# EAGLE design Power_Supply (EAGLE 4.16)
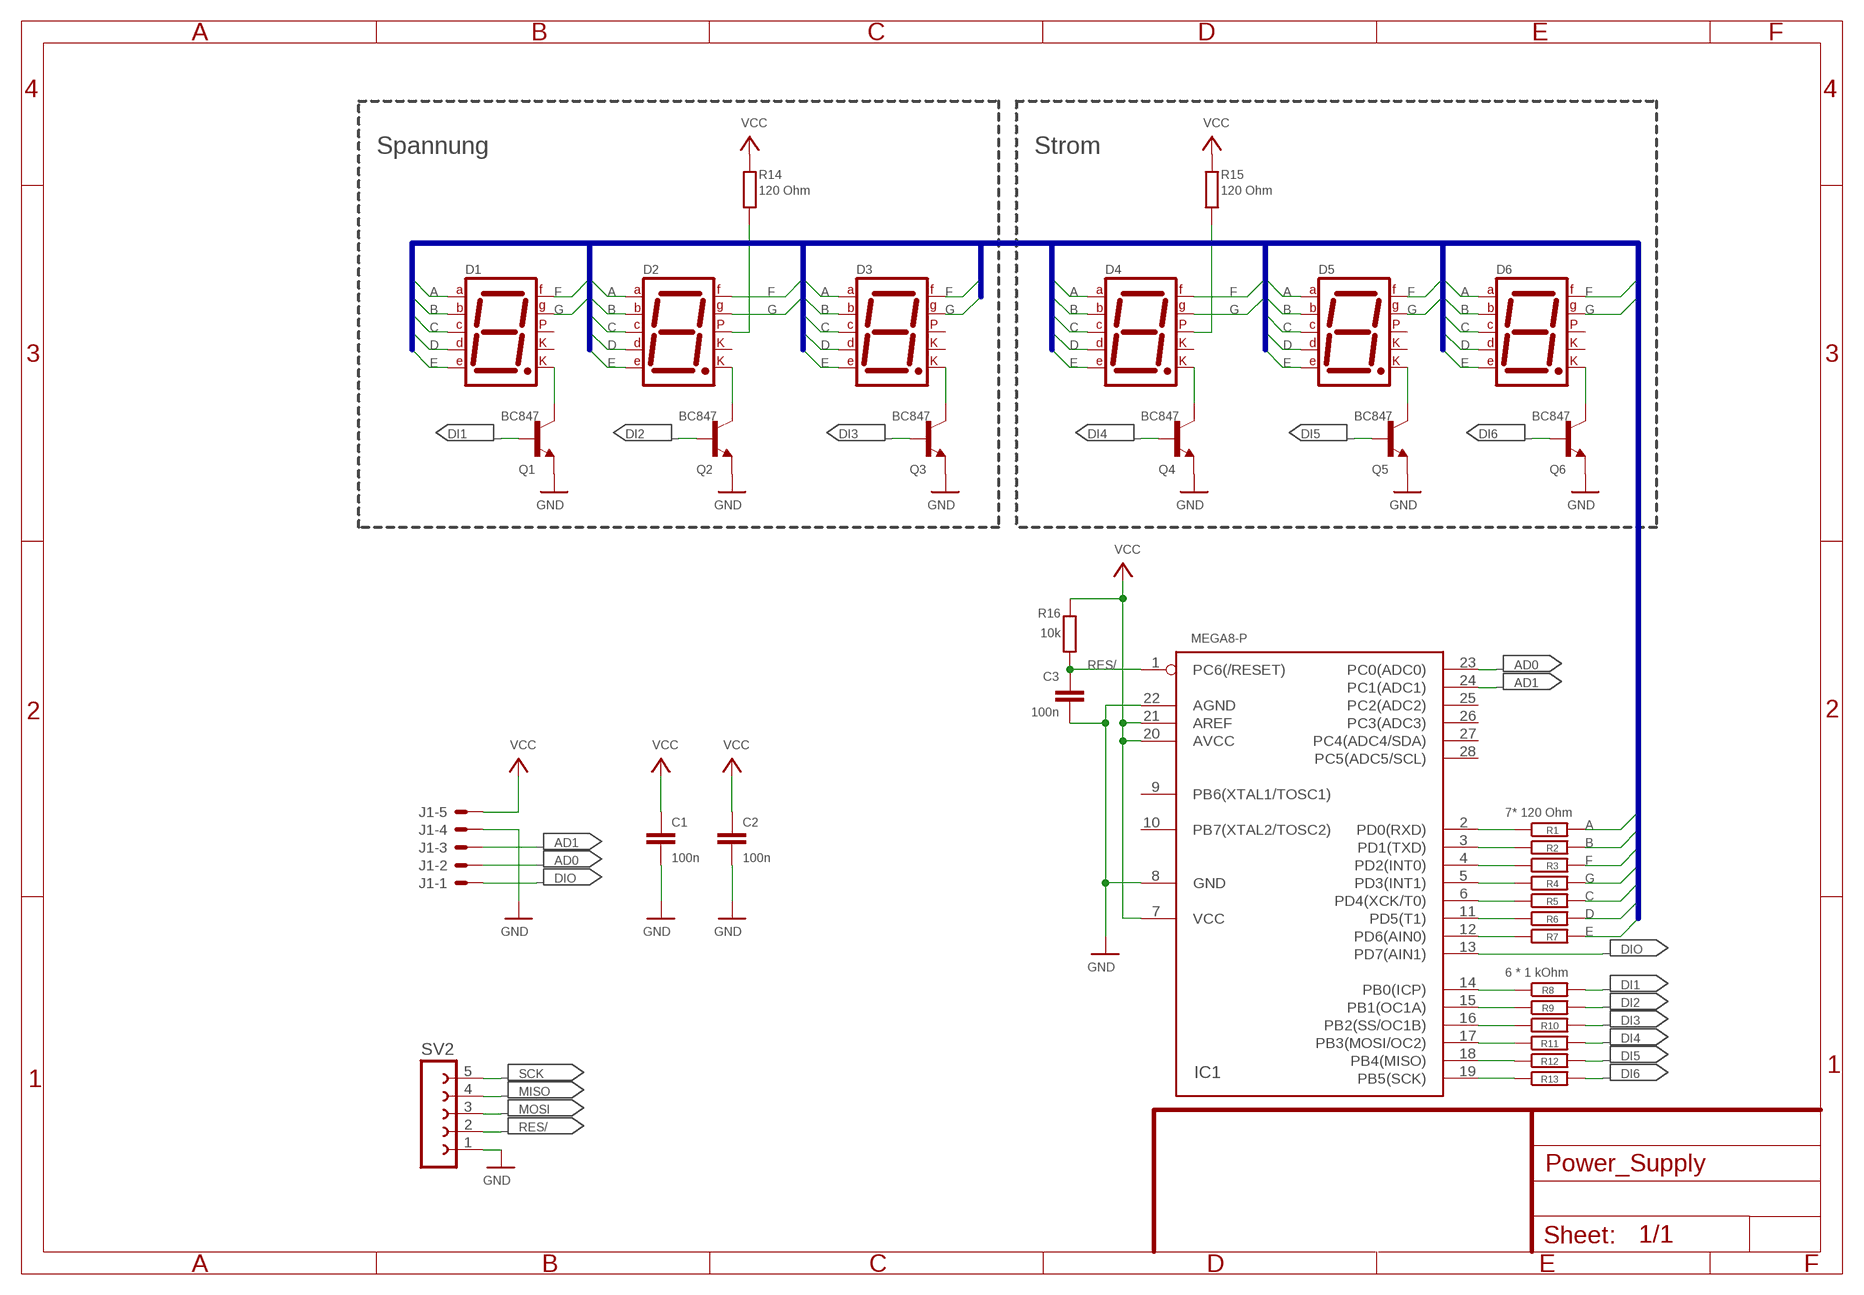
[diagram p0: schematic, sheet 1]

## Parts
C1  100n  C-EU025-025X050  [C025-025X050]
C2  100n  C-EU025-025X050  [C025-025X050]
C3  100n  C-EU025-025X050  [C025-025X050]
D1  7SEG-CK  [7SEG-13]
D2  7SEG-CK  [7SEG-13]
D3  7SEG-CK  [7SEG-13]
D4  7SEG-CK  [7SEG-13]
D5  7SEG-CK  [7SEG-13]
D6  7SEG-CK  [7SEG-13]
IC1  MEGA8-P  [DIL28-3]
J1  22-27-2051-05  [6410-05]
Q1  BC847  BC847BSMD  [SOT23]
Q2  BC847  BC847BSMD  [SOT23]
Q3  BC847  BC847BSMD  [SOT23]
Q4  BC847  BC847BSMD  [SOT23]
Q5  BC847  BC847BSMD  [SOT23]
Q6  BC847  BC847BSMD  [SOT23]
R1  7* 120 Ohm  R-EU_0207/10  [0207/10]
R2  R-EU_0207/10  [0207/10]
R3  R-EU_0207/10  [0207/10]
R4  R-EU_0207/10  [0207/10]
R5  R-EU_0207/10  [0207/10]
R6  R-EU_0207/10  [0207/10]
R7  R-EU_0207/10  [0207/10]
R8  6 * 1 kOhm  R-EU_0207/10  [0207/10]
R9  R-EU_0207/10  [0207/10]
R10  R-EU_0207/10  [0207/10]
R11  R-EU_0207/10  [0207/10]
R12  R-EU_0207/10  [0207/10]
R13  R-EU_0207/10  [0207/10]
R14  120 Ohm  R-EU_0207/10  [0207/10]
R15  120 Ohm  R-EU_0207/10  [0207/10]
R16  10k  R-EU_0207/10  [0207/10]
SV2  FE05-1  [FE05-1]

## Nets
A: D1.7(A) D2.7(A) D3.7(A) D4.7(A) D5.7(A) D6.7(A) R1.2
AD0: IC1.23(PC0(ADC0)) J1.2
AD1: IC1.24(PC1(ADC1)) J1.3
B: D1.6(B) D2.6(B) D3.6(B) D4.6(B) D5.6(B) D6.6(B) R2.2
C: D1.4(C) D2.4(C) D3.4(C) D4.4(C) D5.4(C) D6.4(C) R5.2
D: D1.2(D) D2.2(D) D3.2(D) D4.2(D) D5.2(D) D6.2(D) R6.2
DI1: Q1.1(B) R8.2
DI2: Q2.1(B) R9.2
DI3: Q3.1(B) R10.2
DI4: Q4.1(B) R11.2
DI5: Q5.1(B) R12.2
DI6: Q6.1(B) R13.2
DIO: IC1.13(PD7(AIN1)) J1.1
E: D1.1(E) D2.1(E) D3.1(E) D4.1(E) D5.1(E) D6.1(E) R7.2
F: D1.9(F) D2.9(F) D3.9(F) D4.9(F) D5.9(F) D6.9(F) R3.2
G: D1.10(G) D2.10(G) D3.10(G) D4.10(G) D5.10(G) D6.10(G) R4.2
GND: C1.2 C2.2 C3.2 IC1.8(GND) IC1.22(AGND) J1.4 Q1.2(E) Q2.2(E) Q3.2(E) Q4.2(E) Q5.2(E) Q6.2(E) SV2.1
MISO: IC1.18(PB4(MISO)) R12.1 SV2.4
MOSI: IC1.17(PB3(MOSI/OC2)) R11.1 SV2.3
N$1: IC1.2(PD0(RXD)) R1.1
N$2: IC1.3(PD1(TXD)) R2.1
N$3: IC1.4(PD2(INT0)) R3.1
N$4: IC1.5(PD3(INT1)) R4.1
N$5: IC1.6(PD4(XCK/T0)) R5.1
N$6: IC1.11(PD5(T1)) R6.1
N$7: IC1.12(PD6(AIN0)) R7.1
N$8: D1.8(CK2) Q1.3(C)
N$9: D2.8(CK2) Q2.3(C)
N$10: D3.8(CK2) Q3.3(C)
N$11: D4.8(CK2) Q4.3(C)
N$12: D5.8(CK2) Q5.3(C)
N$13: D6.8(CK2) Q6.3(C)
N$14: IC1.14(PB0(ICP)) R8.1
N$15: IC1.15(PB1(OC1A)) R9.1
N$16: IC1.16(PB2(SS/OC1B)) R10.1
N$20: D2.5(DP) R14.1
N$21: D4.5(DP) R15.1
RES/: C3.1 IC1.1(PC6(/RESET)) R16.1 SV2.2
SCK: IC1.19(PB5(SCK)) R13.1 SV2.5
VCC: C1.1 C2.1 IC1.7(VCC) IC1.20(AVCC) IC1.21(AREF) J1.5 R14.2 R15.2 R16.2
Unconnected: D1.3(CK1) D1.5(DP) D2.3(CK1) D3.3(CK1) D3.5(DP) D4.3(CK1) D5.3(CK1) D5.5(DP) D6.3(CK1) D6.5(DP) IC1.9(PB6(XTAL1/TOSC1)) IC1.10(PB7(XTAL2/TOSC2)) IC1.25(PC2(ADC2)) IC1.26(PC3(ADC3)) IC1.27(PC4(ADC4/SDA)) IC1.28(PC5(ADC5/SCL))

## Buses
A,B,C,D,E,F,G

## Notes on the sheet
- Spannung | Strom

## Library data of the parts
C1-C3 = rcl:C-EU: CAPACITOR, European symbol
D1-D6 = special:7SEG-CK: 7-segment DISPLAY single cathode, 13 mm
IC1 = avr-1:MEGA8-P: MICROCONTROLLER 8 Kbytes FLASH 1 kbytes SRAM 512 bytes EEPROM USART 4-channel 10 bit ADC 2-channel 8 bit ADC
J1 = con-molex:22-?-05: CONNECTOR wire to board 2.54 mm (.1 inch) pitch header
Q1-Q6 = transistor-npn:BC847*: NPN Transistor
R1-R16 = rcl:R-EU_: RESISTOR, European symbol
SV2 = con-lsta:FE05-1: FEMALE HEADER

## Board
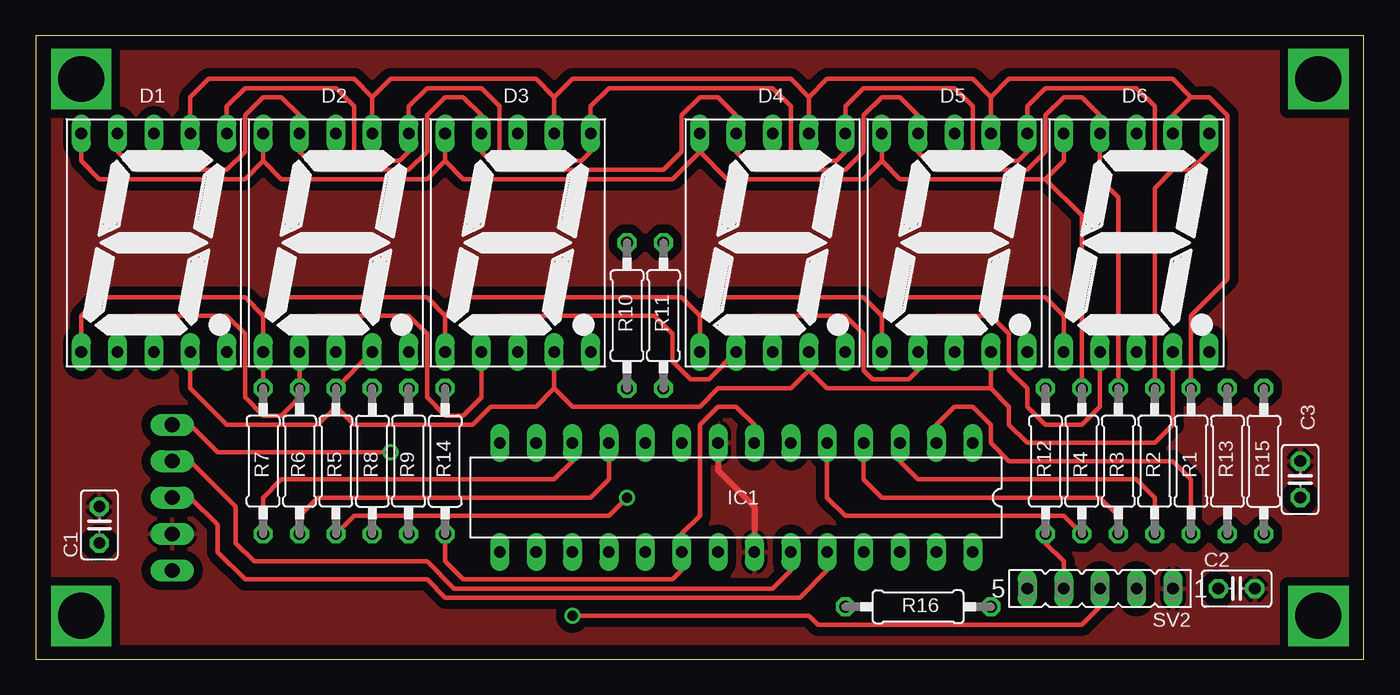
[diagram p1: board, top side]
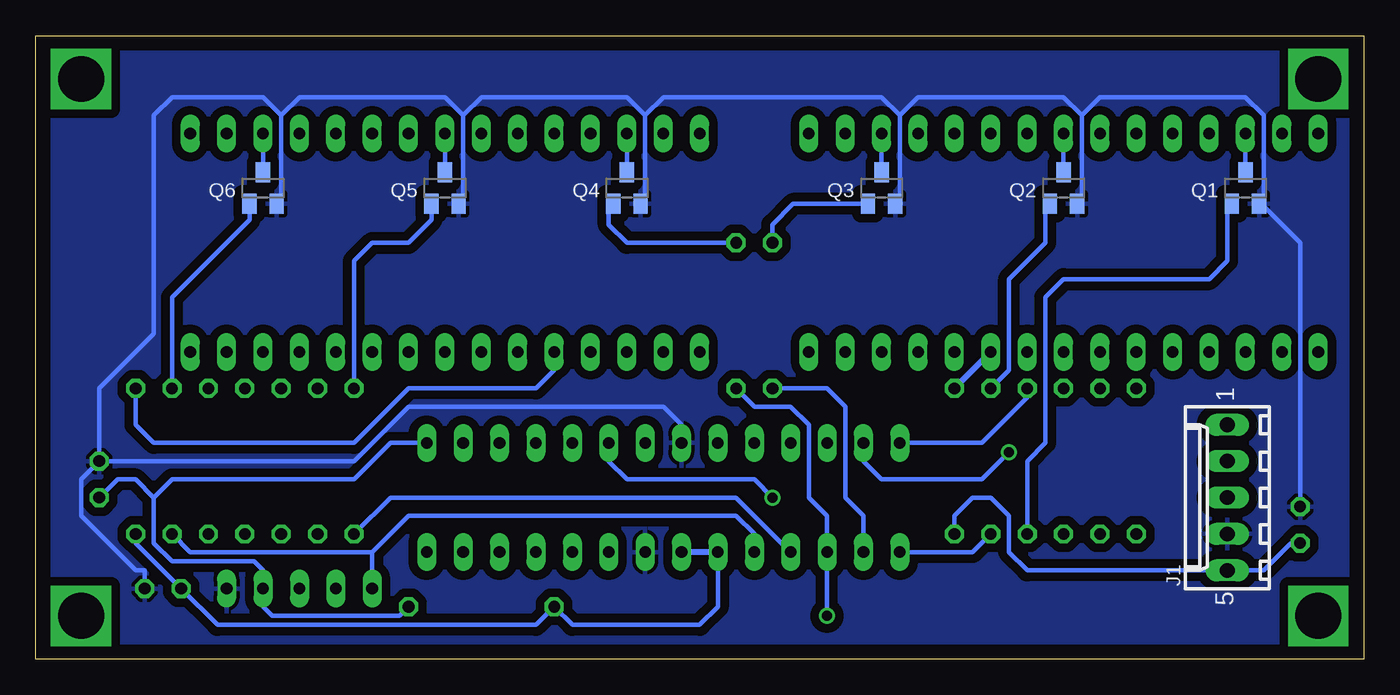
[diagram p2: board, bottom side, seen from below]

Size 92.69 x 43.48 mm. Coordinates in mm from the lower left corner, seen from the top.
Outline: 0,0 92.69,0 92.69,43.48 0,43.48 0,0
Copper layers (1*16): Top 0.035mm / dielectric 1.5mm / Bottom 0.035mm
Design rules "default": minimum track width 10mil, minimum drill 24mil, track to track 8mil, track to pad 8mil, pad to pad 8mil, via to via 8mil, smd to smd 8mil, copper to edge 40mil, drill to drill 8mil, minimum pad ring 10mil, minimum via ring 8mil, stop-mask expansion 4mil, vias tented up to drill 0mil, thermal gap 10mil

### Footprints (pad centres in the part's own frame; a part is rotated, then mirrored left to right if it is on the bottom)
C025-025X050 = drill 0.813 octagon: 1 -1.27,0; 2 1.27,0
7SEG-13 = drill 0.813 long: 1 -5.08,-7.62; 2 -2.54,-7.62; 3 0,-7.62; 4 2.54,-7.62; 5 5.08,-7.62; 6 5.08,7.62; 7 2.54,7.62; 8 0,7.62; 9 -2.54,7.62; 10 -5.08,7.62
DIL28-3 = drill 0.813 long: 1 -16.51,-3.81; 2 -13.97,-3.81; 3 -11.43,-3.81; 4 -8.89,-3.81; 5 -6.35,-3.81; 6 -3.81,-3.81; 7 -1.27,-3.81; 8 1.27,-3.81; 9 3.81,-3.81; 10 6.35,-3.81; 11 8.89,-3.81; 12 11.43,-3.81; 13 13.97,-3.81; 14 16.51,-3.81; 15 16.51,3.81; 16 13.97,3.81; 17 11.43,3.81; 18 8.89,3.81; 19 6.35,3.81; 20 3.81,3.81; 21 1.27,3.81; 22 -1.27,3.81; 23 -3.81,3.81; 24 -6.35,3.81; 25 -8.89,3.81; 26 -11.43,3.81; 27 -13.97,3.81; 28 -16.51,3.81
6410-05 = drill 1.016 long: 1 5.08,0; 2 2.54,0; 3 0,0; 4 -2.54,0; 5 -5.08,0
SOT23 = smd 1 x 1.4: 1 -0.95,-1.1; 2 0.95,-1.1; 3 0,1.1
0207/10 = drill 0.813 octagon: 1 -5.08,0; 2 5.08,0
FE05-1 = drill 0.813 long: 1 -5.08,0; 2 -2.54,0; 3 0,0; 4 2.54,0; 5 5.08,0

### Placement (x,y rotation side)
C1  4.44,9.36 90 top
C2  83.81,4.92 0 top
C3  88.26,12.54 90 top
D1  8.25,29.05 0 top
D2  20.95,29.05 0 top
D3  33.65,29.05 0 top
D4  51.43,29.05 0 top
D5  64.13,29.05 0 top
D6  76.83,29.05 0 top
IC1  48.89,11.27 180 top
J1  9.52,11.27 90 bottom
Q1  8.25,32.86 0 bottom
Q2  20.95,32.86 0 bottom
Q3  33.65,32.86 0 bottom
Q4  51.43,32.86 0 bottom
Q5  64.13,32.86 0 bottom
Q6  76.83,32.86 0 bottom
R1  80.64,13.81 90 top
R2  78.1,13.81 90 top
R3  75.56,13.81 90 top
R4  73.02,13.81 90 top
R5  20.95,13.81 90 top
R6  18.41,13.81 90 top
R7  15.87,13.81 90 top
R8  23.49,13.81 270 top
R9  26.03,13.81 90 top
R10  41.27,23.96 90 top
R11  43.81,23.96 90 top
R12  70.48,13.81 90 top
R13  83.18,13.81 90 top
R14  28.57,13.81 270 top
R15  85.72,13.81 270 top
R16  61.59,3.65 180 top
SV2  74.29,4.92 180 top

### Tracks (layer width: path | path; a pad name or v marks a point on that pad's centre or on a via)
A
  Top 0.305: D1.7 10.79,39.2 12.06,40.48 22.22,40.48 23.49,39.2 | 23.49,39.2 D2.7 | 23.49,39.2 24.76,40.48 34.92,40.48 36.19,39.2 | 36.19,39.2 D3.7 | 36.19,39.2 37.46,40.48 52.7,40.48 53.97,39.2 | 53.97,39.2 D4.7 | 53.97,39.2 55.24,40.48 65.4,40.48 66.67,39.2 | 66.67,39.2 D5.7 | 66.67,39.2 67.94,40.48 79.37,40.48 80.64,39.2 | R1.2 80.64,23.96 83.18,26.51 83.18,37.94 81.91,39.2 80.64,39.2 | D6.7 79.37,37.94 80.64,39.2
AD0
  Top 0.305: IC1.23 52.7,6.18 51.43,4.92 29.2,4.92 27.3,6.82 15.23,6.82 13.96,8.09 13.96,10.63 10.79,13.81 J1.2
AD1
  Top 0.305: IC1.24 55.24,6.18 53.34,4.28 28.57,4.28 27.3,5.55 14.6,5.55 12.7,7.46 12.7,9.36 10.79,11.27 J1.3
B
  Top 0.305: D1.6 13.33,38.57 14.6,39.84 20.95,39.84 22.22,38.57 22.22,35.4 22.86,34.76 25.39,34.76 26.03,35.4 D2.6 26.03,38.57 27.3,39.84 31.11,39.84 32.38,38.57 32.38,35.4 33.02,34.76 38.09,34.76 38.73,35.4 D3.6 38.73,38.57 40,39.84 51.43,39.84 52.7,38.57 52.7,35.4 53.34,34.76 55.88,34.76 56.51,35.4 D4.6 56.51,38.57 57.78,39.84 64.13,39.84 65.4,38.57 65.4,35.4 66.03,34.76 68.58,34.76 69.21,35.4 D5.6 69.21,38.57 70.48,39.84 76.83,39.84 78.1,38.57 78.1,35.4 79.37,34.12 | 79.37,34.12 80.64,34.12 81.91,35.4 D6.6 | 79.37,34.12 78.1,32.86 R2.2
C
  Top 0.305: D1.4 10.79,18.89 13.33,16.35 19.68,16.35 20.95,17.62 | 36.19,18.89 D3.4 | 36.19,18.89 37.46,17.62 46.35,17.62 47.62,18.89 52.7,18.89 53.97,20.16 | 53.97,20.16 D4.4 | 53.97,20.16 55.24,18.89 66.67,18.89 | 66.67,18.89 D5.4 | 66.67,18.89 67.94,17.62 67.94,16.35 69.21,15.08 78.1,15.08 79.37,16.35 D6.4 | 36.19,18.89 34.92,17.62 31.74,17.62 30.47,16.35 22.22,16.35 20.95,17.62 | D2.4 R5.2 20.95,17.62
D
  Top 0.305: D1.2 5.71,22.7 6.98,23.96 13.33,23.96 14.6,22.7 14.6,18.25 15.87,16.98 17.14,16.98 18.41,18.25 R6.2 D2.2 18.41,22.7 19.68,23.96 26.03,23.96 27.3,22.7 27.3,18.25 28.57,16.98 29.84,16.98 31.11,18.25 D3.2 31.11,22.7 32.38,23.96 43.17,23.96 44.45,22.7 44.45,20.79 45.71,19.52 46.98,19.52 D4.2 48.89,22.7 50.16,23.96 56.51,23.96 57.78,22.7 57.78,20.16 58.41,19.52 60.95,19.52 61.59,20.16 D5.2 61.59,22.7 62.86,23.96 66.67,23.96 67.94,22.7 67.94,20.16 69.21,18.89 69.21,17.62 70.48,16.35 73.02,16.35 74.29,17.62 D6.2
DI1
  Bottom 0.305: R8.2 23.49,13.81 22.22,15.08 22.22,25.23 20.95,26.51 10.79,26.51 9.52,27.78 9.52,31.59 9.35,31.76 Q1.1
DI2
  Bottom 0.305: R9.2 24.76,20.16 24.76,26.51 22.22,29.05 22.22,31.59 22.05,31.76 Q2.1
DI3
  Bottom 0.305: Q3.1 39.83,31.76 41.27,30.32 R10.2
DI4
  Bottom 0.305: Q4.1 52.53,31.76 52.7,31.59 52.7,30.32 51.43,29.05 R11.2
DI5
  Bottom 0.305: Q5.1 65.08,30.64 66.67,29.05 69.21,29.05 70.48,27.78 R12.2
DI6
  Bottom 0.305: Q6.1 77.78,30.64 83.18,25.23 R13.2
DIO  (via drill 0.7)
  Top 0.305: v24.76,14.44 12.7,14.44 10.79,16.35 J1.1
  Bottom 0.305: IC1.13 34.92,13.81 33.65,12.54 26.66,12.54 v24.76,14.44
E
  Top 0.305: D1.1 3.17,23.96 4.44,25.23 14.6,25.23 15.87,23.96 | 28.57,23.96 D3.1 | 28.57,23.96 29.84,25.23 45.08,25.23 46.35,23.96 | 59.05,23.96 D5.1 | 59.05,23.96 60.32,25.23 70.48,25.23 71.75,23.96 D6.1 | 15.87,23.96 D2.1 R7.2 | 15.87,23.96 17.14,25.23 27.3,25.23 28.57,23.96 | 46.35,23.96 D4.1 | 46.35,23.96 47.62,25.23 57.78,25.23 59.05,23.96
F
  Top 0.305: D1.9 5.71,35.4 6.98,34.12 13.33,34.12 14.6,35.4 14.6,37.94 15.87,39.2 17.14,39.2 18.41,37.94 D2.9 18.41,35.4 19.68,34.12 26.03,34.12 27.3,35.4 27.3,37.94 28.57,39.2 29.84,39.2 31.11,37.94 D3.9 31.11,35.4 32.38,34.12 43.81,34.12 45.08,35.4 45.08,37.94 46.35,39.2 47.62,39.2 48.89,37.94 D4.9 48.89,35.4 50.16,34.12 56.51,34.12 57.78,35.4 57.78,37.94 59.05,39.2 60.32,39.2 61.59,37.94 D5.9 61.59,35.4 62.86,34.12 69.21,34.12 70.48,35.4 70.48,37.94 71.75,39.2 73.02,39.2 74.29,37.94 D6.9 74.29,33.49 75.56,32.22 R3.2
G
  Top 0.305: D1.10 3.17,34.76 4.44,33.49 14.6,33.49 15.87,34.76 | 15.87,34.76 D2.10 | 15.87,34.76 17.14,33.49 27.3,33.49 28.57,34.76 | 28.57,34.76 D3.10 | 28.57,34.76 29.84,33.49 44.45,33.49 46.35,35.4 | 46.35,35.4 D4.10 | 46.35,35.4 48.26,33.49 57.78,33.49 59.05,34.76 | 59.05,34.76 D5.10 | 59.05,34.76 60.32,33.49 70.48,33.49 | D6.10 71.75,34.76 70.48,33.49 | 70.48,33.49 73.02,30.95 R4.2
GND
  Top 0.406: IC1.8 47.62,13.17 50.16,10.63 IC1.22
  Bottom 0.305: 6.98,31.59 6.98,37.94 8.25,39.2 18.41,39.2 19.68,37.94 | Q2.2 19.85,31.76 19.68,31.59 19.68,37.94 | Q3.2 32.55,31.76 32.38,31.59 32.38,37.94 | 32.38,37.94 31.11,39.2 20.95,39.2 19.68,37.94 | Q4.2 50.33,31.76 50.16,31.59 50.16,37.94 | 50.16,37.94 48.89,39.2 33.65,39.2 32.38,37.94 | 62.86,37.94 61.59,39.2 51.43,39.2 50.16,37.94 | Q6.2 75.73,31.76 75.56,31.59 75.56,37.94 | 75.56,37.94 74.29,39.2 64.13,39.2 62.86,37.94 | Q5.2 63.03,31.76 62.86,31.59 62.86,37.94 | IC1.8 47.62,16.35 48.89,17.62 66.67,17.62 70.48,13.81 C3.2 | C3.2 88.26,18.89 84.45,22.7 84.45,37.94 83.18,39.2 76.83,39.2 75.56,37.94 | 6.98,31.59 7.15,31.76 Q1.2 | 6.98,31.59 4.44,29.05 C1.2 | C2.2 85.08,6.18 85.72,6.18 89.53,10 89.53,12.54 C3.2
  pour Bottom (isolate 0.61): 0.63,43.02 92.07,43.02 92.07,0.47 0.63,0.47
  pour Top (isolate 0.61): 0.63,43.02 0.63,0.47 92.07,0.47 92.07,43.02
MISO
  Top 0.305: R12.1 70.48,8.09 71.75,6.82 SV2.4
  Bottom 0.305: IC1.18 43.81,11.27 67.94,11.27 R12.1
MOSI  (via drill 0.7)
  Top 0.305: SV2.3 74.29,3.65 73.02,2.38 54.6,2.38 53.97,3.01 v37.46,3.01
  Bottom 0.305: R11.1 42.54,17.62 40,17.62 38.73,16.35 38.73,11.27 37.46,10 IC1.17 v37.46,3.01
N$1
  Top 0.305: IC1.2 62.86,16.35 64.13,17.62 65.4,17.62 66.67,16.35 66.67,15.08 67.94,13.81 79.37,13.81 80.64,12.54 R1.1
N$2
  Top 0.305: R2.1 78.1,11.27 76.83,12.54 61.59,12.54 60.32,13.81 IC1.3
N$3
  Top 0.305: IC1.4 57.78,12.54 59.05,11.27 74.29,11.27 75.56,10 R3.1
N$4
  Top 0.305: IC1.5 55.24,11.27 56.51,10 71.75,10 R4.1
N$5  (via drill 0.7)
  Top 0.305: R5.1 22.22,10 40,10 v41.27,11.27
  Bottom 0.305: v41.27,11.27 42.54,12.54 51.43,12.54 52.7,13.81 IC1.6
N$6
  Top 0.305: R6.1 18.41,10 19.68,11.27 38.73,11.27 40,12.54 IC1.11
N$7
  Top 0.305: R7.1 15.87,11.27 17.14,12.54 36.19,12.54 37.46,13.81 IC1.12
N$8
  Bottom 0.305: Q1.3 D1.8
N$9
  Bottom 0.305: Q2.3 D2.8
N$10
  Bottom 0.305: Q3.3 D3.8
N$11
  Bottom 0.305: Q4.3 D4.8
N$12
  Bottom 0.305: Q5.3 D5.8
N$13
  Bottom 0.305: Q6.3 D6.8
N$14
  Bottom 0.305: IC1.14 26.66,15.08 23.49,18.25 R8.1
N$15
  Bottom 0.305: IC1.15 27.3,7.46 R9.1
N$16
  Bottom 0.305: IC1.16 34.92,10 36.19,11.27 36.19,17.62 37.46,18.89 R10.1
N$20
  Bottom 0.406: R14.1 D2.5
N$21
  Bottom 0.305: D4.5 56.51,20.16 57.78,18.89 66.67,18.89 70.48,15.08 84.45,15.08 85.72,16.35 R15.1
N$22  (via drill 3.2 pad 3.81)
  other vias: 3.17,40.48
N$23  (via drill 3.2 pad 3.81)
  other vias: 3.17,3.01
N$24  (via drill 3.2 pad 3.81)
  other vias: 89.53,3.01
N$25  (via drill 3.2 pad 3.81)
  other vias: 89.53,40.48
RES/
  Bottom 0.305: IC1.1 67.94,15.08 70.48,12.54 83.18,12.54 84.45,11.27 | 84.45,11.27 84.45,8.09 83.18,6.82 77.47,6.82 76.83,6.18 SV2.2 76.83,3.65 76.19,3.01 67.3,3.01 R16.1 | 84.45,11.27 85.72,12.54 86.99,12.54 C3.1
SCK
  Bottom 0.305: IC1.19 42.54,8.73 43.81,10 66.67,10 69.21,7.46 | 69.21,7.46 81.91,7.46 R13.1 | 69.21,7.46 SV2.5
VCC
  Top 0.305: IC1.7 50.16,16.35 48.89,17.62 47.62,17.62 46.35,16.35 46.35,10 45.08,8.73 IC1.20 45.08,6.18 44.45,5.55 29.84,5.55 28.57,6.82 R14.2
  Bottom 0.305: R14.2 28.57,10 27.3,11.27 26.03,11.27 24.76,10 24.76,7.46 23.49,6.18 J1.5 6.98,6.18 5.08,8.09 C1.1 | R15.2 85.72,8.09 C2.1 80,2.38 57.78,2.38 R16.2 55.24,2.38 46.35,2.38 45.08,3.65 IC1.20
  Bottom 0.406: IC1.20 IC1.21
